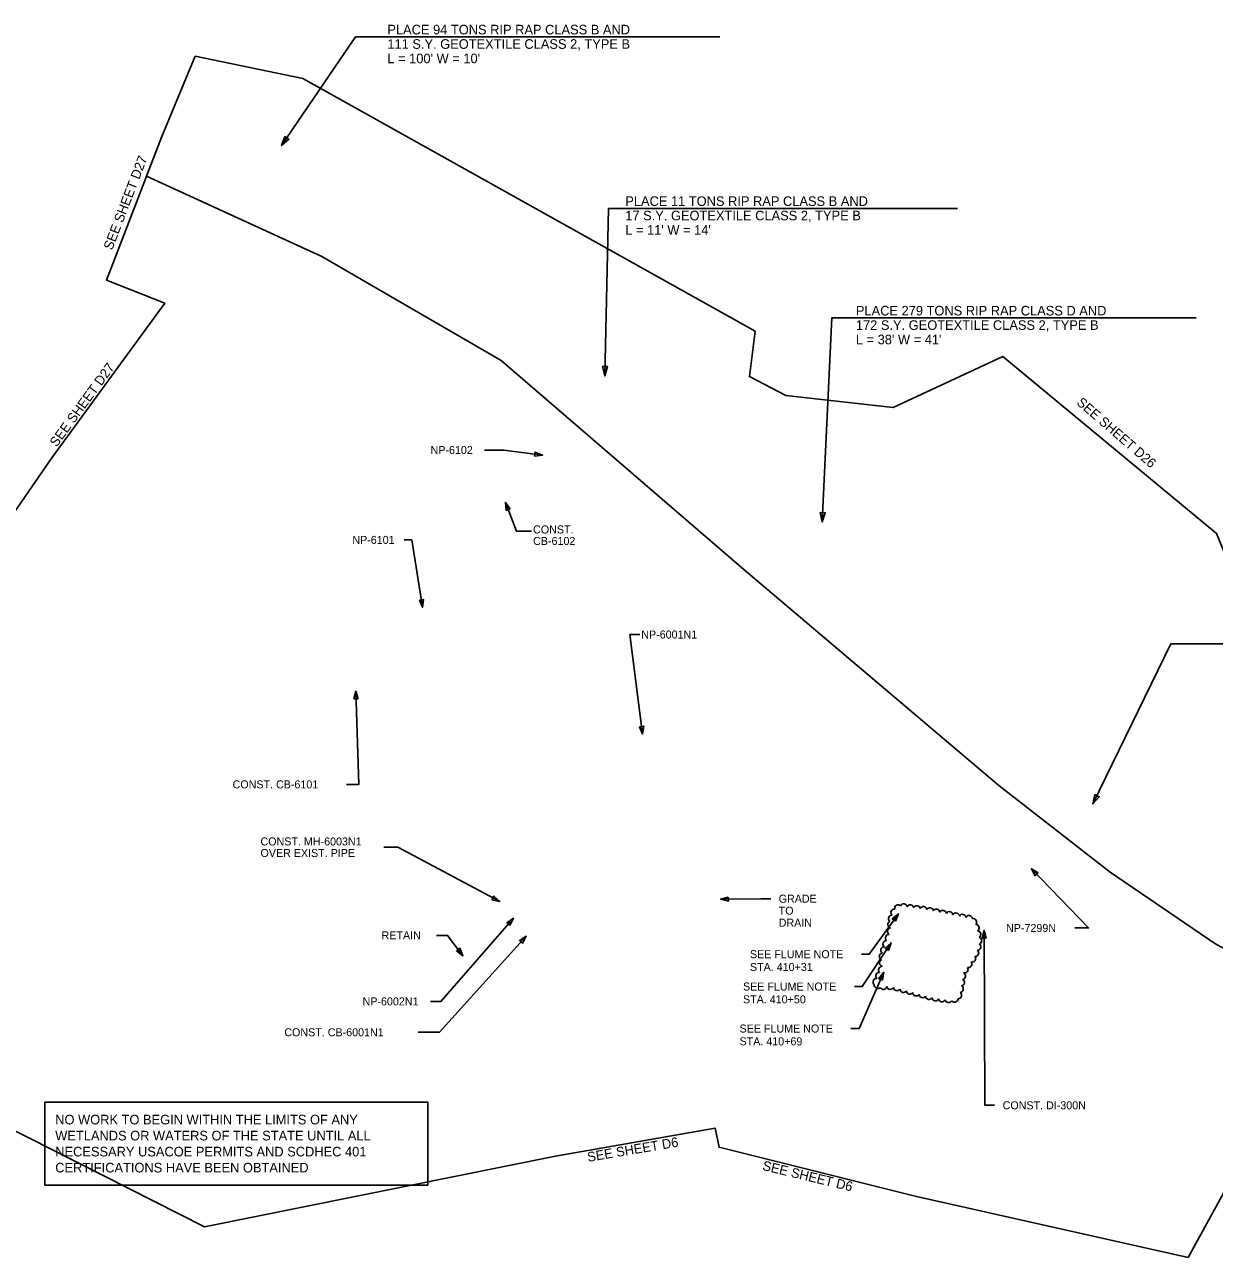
# Model space of a CAD drawing. Extents: x 1608789 to 1610795, y 1093162 to 1094361.
# Drawn here: x 1609302 to 1610045, y 1093583 to 1094353 of the extents above; entities that cross this region are included whole.
import ezdxf

# ---------------------------------------------------------------- set-up
doc = ezdxf.new("R2010")
doc.units = 0
for name, color, linetype in [('Default', 7, 'Continuous'), ('NOI', 7, 'Continuous'), ('Plan_Clip', 7, 'Continuous'), ('RD_SHT_MatchLine', 7, 'Continuous'), ('RD_TX_Drainage', 7, 'Continuous')]:
    doc.layers.add(name, color=color, linetype=linetype)

msp = doc.modelspace()

# ---------------------------------------------------------------- linework, layer by layer
at = {"layer": 'Default'}
for points in [[(1609824.92, 1093772.82), (1609829.86, 1093772.82), (1609848.1, 1093798.11)], [(1609820.57, 1093752.62), (1609825.41, 1093752.62), (1609843.52, 1093779.96)], [(1609818.42, 1093726.38), (1609823.49, 1093726.38), (1609838.91, 1093761.53)]]:
    msp.add_lwpolyline(points, dxfattribs=at)
for points in [[(1609846.33, 1093793.43), (1609848.1, 1093798.11), (1609844.23, 1093794.95)], [(1609841.93, 1093775.22), (1609843.52, 1093779.96), (1609839.77, 1093776.65)], [(1609838.15, 1093756.58), (1609838.91, 1093761.53), (1609835.78, 1093757.62)]]:
    msp.add_lwpolyline(points, close=True, dxfattribs=at)
at = {"layer": 'NOI'}
msp.add_lwpolyline([(1609314.79, 1093680.42), (1609554.06, 1093680.42), (1609554.06, 1093628.56), (1609314.79, 1093628.56)], close=True, dxfattribs=at)
at = {"layer": 'Plan_Clip'}
for points in [[(1609408.82, 1094333.76), (1609476.05, 1094319.7), (1609758.48, 1094161.88), (1609754.93, 1094133.63), (1609777.73, 1094121.71), (1609844.69, 1094114.18), (1609913.32, 1094146.13), (1610046.84, 1094035.59), (1610143.39, 1093801.2), (1610070, 1093658.12), (1610028.96, 1093583.46), (1609859.36, 1093621.37), (1609735.98, 1093652.25), (1609733.52, 1093664.22), (1609633.89, 1093646.58), (1609414.5, 1093602.61), (1609098.34, 1093762.73), (1609319.26, 1094082.92), (1609389.72, 1094179.44), (1609353.45, 1094193.74), (1609387.82, 1094283.49)], [(1609408.82, 1094333.76), (1609476.05, 1094319.7), (1609758.48, 1094161.88), (1609754.93, 1094133.63), (1609777.73, 1094121.71), (1609844.69, 1094114.18), (1609913.32, 1094146.13), (1610046.84, 1094035.59), (1610143.39, 1093801.2), (1610070, 1093658.12), (1610028.96, 1093583.46), (1609859.36, 1093621.37), (1609735.98, 1093652.25), (1609733.52, 1093664.22), (1609633.89, 1093646.58), (1609414.5, 1093602.61), (1609098.34, 1093762.73), (1609319.26, 1094082.92), (1609389.72, 1094179.44), (1609353.45, 1094193.74), (1609387.82, 1094283.49)], [(1609408.82, 1094333.76), (1609476.05, 1094319.7), (1609758.48, 1094161.88), (1609754.93, 1094133.63), (1609777.73, 1094121.71), (1609844.69, 1094114.18), (1609913.32, 1094146.13), (1610046.84, 1094035.59), (1610143.39, 1093801.2), (1610070, 1093658.12), (1610028.96, 1093583.46), (1609859.36, 1093621.37), (1609735.98, 1093652.25), (1609733.52, 1093664.22), (1609633.89, 1093646.58), (1609414.5, 1093602.61), (1609098.34, 1093762.73), (1609319.26, 1094082.92), (1609389.72, 1094179.44), (1609353.45, 1094193.74), (1609387.82, 1094283.49)], [(1609408.82, 1094333.76), (1609476.05, 1094319.7), (1609758.48, 1094161.88), (1609754.93, 1094133.63), (1609777.73, 1094121.71), (1609844.69, 1094114.18), (1609913.32, 1094146.13), (1610046.84, 1094035.59), (1610143.39, 1093801.2), (1610070, 1093658.12), (1610028.96, 1093583.46), (1609859.36, 1093621.37), (1609735.98, 1093652.25), (1609733.52, 1093664.22), (1609633.89, 1093646.58), (1609414.5, 1093602.61), (1609098.34, 1093762.73), (1609319.26, 1094082.92), (1609389.72, 1094179.44), (1609353.45, 1094193.74), (1609387.82, 1094283.49)], [(1609408.82, 1094333.76), (1609476.05, 1094319.7), (1609758.48, 1094161.88), (1609754.93, 1094133.63), (1609777.73, 1094121.71), (1609844.69, 1094114.18), (1609913.32, 1094146.13), (1610046.84, 1094035.59), (1610143.39, 1093801.2), (1610070, 1093658.12), (1610028.96, 1093583.46), (1609859.36, 1093621.37), (1609735.98, 1093652.25), (1609733.52, 1093664.22), (1609633.89, 1093646.58), (1609414.5, 1093602.61), (1609098.34, 1093762.73), (1609319.26, 1094082.92), (1609389.72, 1094179.44), (1609353.45, 1094193.74), (1609387.82, 1094283.49)], [(1609408.82, 1094333.76), (1609476.05, 1094319.7), (1609758.48, 1094161.88), (1609754.93, 1094133.63), (1609777.73, 1094121.71), (1609844.69, 1094114.18), (1609913.32, 1094146.13), (1610046.84, 1094035.59), (1610143.39, 1093801.2), (1610070, 1093658.12), (1610028.96, 1093583.46), (1609859.36, 1093621.37), (1609735.98, 1093652.25), (1609733.52, 1093664.22), (1609633.89, 1093646.58), (1609414.5, 1093602.61), (1609098.34, 1093762.73), (1609319.26, 1094082.92), (1609389.72, 1094179.44), (1609353.45, 1094193.74), (1609387.82, 1094283.49)], [(1609408.82, 1094333.76), (1609476.05, 1094319.7), (1609758.48, 1094161.88), (1609754.93, 1094133.63), (1609777.73, 1094121.71), (1609844.69, 1094114.18), (1609913.32, 1094146.13), (1610046.84, 1094035.59), (1610143.39, 1093801.2), (1610070, 1093658.12), (1610028.96, 1093583.46), (1609859.36, 1093621.37), (1609735.98, 1093652.25), (1609733.52, 1093664.22), (1609633.89, 1093646.58), (1609414.5, 1093602.61), (1609098.34, 1093762.73), (1609319.26, 1094082.92), (1609389.72, 1094179.44), (1609353.45, 1094193.74), (1609387.82, 1094283.49)], [(1609408.82, 1094333.76), (1609476.05, 1094319.7), (1609758.48, 1094161.88), (1609754.93, 1094133.63), (1609777.73, 1094121.71), (1609844.69, 1094114.18), (1609913.32, 1094146.13), (1610046.84, 1094035.59), (1610143.39, 1093801.2), (1610070, 1093658.12), (1610113.1, 1093742.16), (1610045.7, 1093779.59), (1609980.23, 1093824), (1609910.75, 1093878.22), (1609751.43, 1094013.11), (1609599.85, 1094143.63), (1609487.87, 1094208.49), (1609378.34, 1094258.75), (1609387.82, 1094283.49)]]:
    msp.add_lwpolyline(points, close=True, dxfattribs=at)
at = {"layer": 'RD_TX_Drainage'}
for p, q in [((1609736.41, 1094345.81), (1609521.42, 1094345.81)), ((1609885.02, 1094238.67), (1609670.03, 1094238.67)), ((1610034.11, 1094170.25), (1609815.03, 1094170.25))]:
    msp.add_line(p, q, dxfattribs=at)
for points in [[(1609521.42, 1094345.81), (1609508.99, 1094345.81), (1609462.72, 1094277.89)], [(1609670.03, 1094238.67), (1609667.03, 1094238.67), (1609664.6, 1094134.04)], [(1609815.03, 1094170.25), (1609806.43, 1094170.25), (1609800.51, 1094042.8)], [(1609589.48, 1094087.73), (1609601.51, 1094087.73), (1609625.72, 1094084.54)], [(1609618.85, 1094037.01), (1609609.47, 1094037.01), (1609602.53, 1094055)], [(1609539.35, 1094031.59), (1609544.09, 1094031.59), (1609550.83, 1093989.48)], [(1609686.42, 1093972.49), (1609680.37, 1093972.49), (1609688.26, 1093910.29)], [(1610056.72, 1093966.7), (1610018.3, 1093966.7), (1609969.52, 1093866.63)], [(1609503.27, 1093878.88), (1609511.08, 1093878.88), (1609509.01, 1093937.09)], [(1609526.62, 1093839.63), (1609535.38, 1093839.63), (1609599, 1093805.72)], [(1609958.17, 1093789.19), (1609966.83, 1093789.19), (1609931.12, 1093826.15)], [(1609768.26, 1093807.48), (1609762.06, 1093807.48), (1609736.97, 1093807.18)], [(1609555.66, 1093743.33), (1609562.26, 1093743.33), (1609607.61, 1093795.27)], [(1609908.16, 1093678.42), (1609902.04, 1093678.42), (1609901.55, 1093787.71)], [(1609547.97, 1093724.04), (1609561.43, 1093724.04), (1609615.54, 1093784.03)], [(1609559.6, 1093784.59), (1609566.47, 1093784.59), (1609576.02, 1093771.87)]]:
    msp.add_lwpolyline(points, dxfattribs=at)
for points in [[(1609464.7, 1094283.56), (1609462.72, 1094277.89), (1609467.27, 1094281.81)], [(1609663.18, 1094139.87), (1609664.6, 1094134.04), (1609666.28, 1094139.8)], [(1609620.76, 1094083.88), (1609625.72, 1094084.54), (1609621.1, 1094086.45)], [(1609605.47, 1094050.96), (1609602.53, 1094055), (1609603.06, 1094050.03)], [(1609799.23, 1094048.66), (1609800.51, 1094042.8), (1609802.33, 1094048.52)], [(1609548.79, 1093994.04), (1609550.83, 1093989.48), (1609551.34, 1093994.45)], [(1609510.47, 1093932.31), (1609509.01, 1093937.09), (1609507.89, 1093932.22)], [(1609686.37, 1093914.92), (1609688.26, 1093910.29), (1609688.94, 1093915.24)], [(1609970.67, 1093872.52), (1609969.52, 1093866.63), (1609973.46, 1093871.16)], [(1609935.41, 1093823.58), (1609931.12, 1093826.15), (1609933.55, 1093821.78)], [(1609594.13, 1093806.85), (1609599, 1093805.72), (1609595.34, 1093809.14)], [(1609741.78, 1093808.53), (1609736.97, 1093807.18), (1609741.81, 1093805.95)], [(1609605.41, 1093790.78), (1609607.61, 1093795.27), (1609603.46, 1093792.49)], [(1609902.87, 1093782.88), (1609901.55, 1093787.71), (1609900.28, 1093782.87)], [(1609613.27, 1093779.58), (1609615.54, 1093784.03), (1609611.34, 1093781.31)], [(1609572.08, 1093774.96), (1609576.02, 1093771.87), (1609574.15, 1093776.51)]]:
    msp.add_lwpolyline(points, close=True, dxfattribs=at)
for centre, start, end in [((1609847.89, 1093801.49), 47.63726, 192.63726), ((1609851.31, 1093802.15), 9.26646, 154.26646), ((1609855.43, 1093801.55), 9.26646, 154.26646), ((1609859.54, 1093800.96), 9.26646, 154.26646), ((1609844.06, 1093794.99), 86.35933, 231.35933), ((1609845.58, 1093798.84), 85.32094, 230.32094), ((1609863.65, 1093800.36), 9.26646, 154.26646), ((1609867.7, 1093799.66), 6.13005, 151.13005), ((1609871.77, 1093798.85), 6.13005, 151.13005), ((1609875.84, 1093798.03), 6.13005, 151.13005), ((1609879.92, 1093797.21), 6.13005, 151.13005), ((1609883.99, 1093796.39), 6.13005, 151.13005), ((1609888.06, 1093795.57), 6.13005, 151.13005), ((1609892.13, 1093794.75), 6.13005, 151.13005), ((1609843.42, 1093787), 96.11626, 241.11626), ((1609843.59, 1093791.31), 114.31222, 259.31222), ((1609894.78, 1093792.86), 317.72638, 102.72638), ((1609896.29, 1093789.22), 302.45765, 87.45765), ((1609840.58, 1093779.13), 87.9537, 232.9537), ((1609842.11, 1093782.93), 83.21775, 228.21775), ((1609897.36, 1093785.21), 302.45765, 87.45765), ((1609897.94, 1093781.27), 289.2519, 74.2519), ((1609838.3, 1093771.34), 101.17765, 246.17765), ((1609839.19, 1093775.22), 87.9537, 232.9537), ((1609896.02, 1093773.57), 266.38165, 51.38165), ((1609897.39, 1093777.45), 269.53616, 54.53616), ((1609837.76, 1093763.07), 83.73956, 228.73956), ((1609838.36, 1093767.39), 115.38247, 260.38247), ((1609889.4, 1093763.26), 252.55783, 37.55783), ((1609891.78, 1093766.66), 252.55783, 37.55783), ((1609894.15, 1093770.07), 252.55783, 37.55783), ((1609834.41, 1093755.47), 83.73956, 228.73956), ((1609836.08, 1093759.27), 83.73956, 228.73956), ((1609887.12, 1093755.12), 279.82343, 64.82343), ((1609887.75, 1093759.24), 277.8215, 62.8215), ((1609835.13, 1093753.56), 172.82711, 317.82711), ((1609838.73, 1093752.99), 204.1261, 349.1261), ((1609843.01, 1093753), 190.9246, 335.9246), ((1609847.17, 1093752.19), 182.17482, 327.17482), ((1609851.18, 1093751.09), 182.17482, 327.17482), ((1609855.18, 1093749.99), 182.17482, 327.17482), ((1609886.43, 1093751.07), 275.96607, 60.96607), ((1609859.19, 1093748.9), 182.17482, 327.17482), ((1609863.19, 1093747.8), 182.17482, 327.17482), ((1609867.2, 1093746.7), 182.17482, 327.17482), ((1609871.18, 1093745.88), 189.41854, 334.41854), ((1609875.29, 1093745.3), 189.52791, 334.52791), ((1609879.41, 1093744.7), 188.96314, 333.96314), ((1609883.15, 1093744.98), 214.64771, 359.64771), ((1609885.37, 1093747.14), 268.79375, 53.79375)]:
    msp.add_arc(centre, 2.18, start, end, dxfattribs=at)

# ---------------------------------------------------------------- texts
at = {"layer": 'Default'}
for s, p in [('SEE FLUME NOTE', (1609755.32, 1093770.32)), ('STA. 410+31', (1609755.32, 1093762.32)), ('SEE FLUME NOTE', (1609750.97, 1093750.12)), ('STA. 410+50', (1609750.97, 1093742.12)), ('SEE FLUME NOTE', (1609748.82, 1093723.88)), ('STA. 410+69', (1609748.82, 1093715.88))]:
    msp.add_text(s, height=5, dxfattribs=at).set_placement(p)
at = {"layer": 'NOI'}
for s, p in [('NO WORK TO BEGIN WITHIN THE LIMITS OF ANY', (1609321.34, 1093666.49)), ('WETLANDS OR WATERS OF THE STATE UNTIL ALL', (1609321.34, 1093656.49)), ('NECESSARY USACOE PERMITS AND SCDHEC 401', (1609321.34, 1093646.49)), ('CERTIFICATIONS HAVE BEEN OBTAINED', (1609321.34, 1093636.49))]:
    msp.add_text(s, height=6, rotation=0.00149, dxfattribs=at).set_placement(p)
at = {"layer": 'RD_SHT_MatchLine'}
for s, rotation, p in [('SEE SHEET D27', 69.04646, (1609356.89, 1094212.21)), ('SEE SHEET D27', 53.88241, (1609322.22, 1094089.23)), ('SEE SHEET D26', 319.07383, (1609958.93, 1094116.66)), ('SEE SHEET D6', 9.61851, (1609654.23, 1093643.06)), ('SEE SHEET D6', 346.37, (1609762.74, 1093638.1))]:
    msp.add_text(s, height=6, rotation=rotation, dxfattribs=at).set_placement(p)
at = {"layer": 'RD_TX_Drainage'}
for s, p in [('PLACE 94 TONS RIP RAP CLASS B AND', (1609528.8, 1094347.31)), ('111 S.Y. GEOTEXTILE CLASS 2, TYPE B', (1609528.8, 1094338.31)), ("L = 100' W = 10'", (1609528.8, 1094329.31)), ('PLACE 11 TONS RIP RAP CLASS B AND', (1609677.42, 1094240.17)), ('17 S.Y. GEOTEXTILE CLASS 2, TYPE B', (1609677.42, 1094231.17)), ("L = 11' W = 14'", (1609677.42, 1094222.17)), ('PLACE 279 TONS RIP RAP CLASS D AND', (1609821.48, 1094171.75)), ('172 S.Y. GEOTEXTILE CLASS 2, TYPE B', (1609821.48, 1094162.75)), ("L = 38' W = 41'", (1609821.48, 1094153.75))]:
    msp.add_text(s, height=6, rotation=360, dxfattribs=at).set_placement(p)
for s, p in [('NP-6102', (1609555.8, 1094085.23)), ('NP-6101', (1609506.93, 1094029.09)), ('CONST. ', (1609619.85, 1094035.61)), ('CB-6102', (1609619.85, 1094028.41)), ('NP-6001N1', (1609687.42, 1093969.99)), ('CONST. CB-6101', (1609432.13, 1093876.38)), ('CONST. MH-6003N1', (1609449.56, 1093840.74)), ('OVER EXIST. PIPE', (1609449.56, 1093833.53)), ('GRADE', (1609773.26, 1093804.98)), ('TO', (1609773.26, 1093797.48)), ('DRAIN', (1609773.26, 1093789.98)), ('NP-7299N', (1609915.29, 1093786.69)), ('RETAIN', (1609525.2, 1093782.09)), ('NP-6002N1', (1609513.32, 1093740.83)), ('CONST. CB-6001N1', (1609464.45, 1093721.54)), ('CONST. DI-300N', (1609913.16, 1093675.92))]:
    msp.add_text(s, height=5, dxfattribs=at).set_placement(p)

doc.saveas('drawing.dxf')
